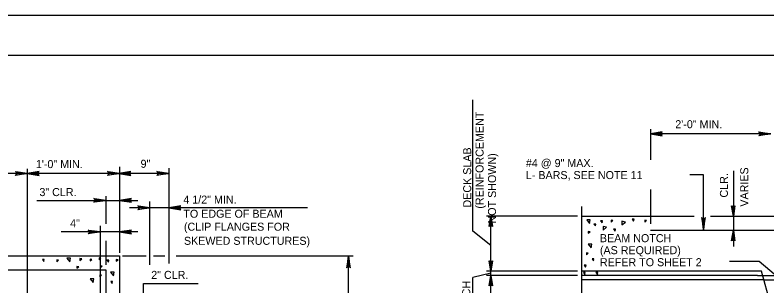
# Model space of a CAD drawing. Extents: x 640009 to 641706, y 298547 to 299735.
# Drawn here: x 640180 to 640461.6, y 299633.8 to 299735.2 of the extents above; entities that cross this region are included whole.
import ezdxf

# ---------------------------------------------------------------- set-up
doc = ezdxf.new("R2010")
doc.units = 0
doc.layers.add('1', color=7, linetype='Continuous')
doc.layers.add('PLT-BNDY', color=7, linetype='Continuous')

msp = doc.modelspace()

# ---------------------------------------------------------------- linework, layer by layer
at = {"layer": '1'}
for p, q in [((640049.47, 299720.17), (640835.47, 299720.17)), ((640049.47, 299720.17), (640835.47, 299720.17)), ((640351.47, 299654.25), (640351.47, 299703.42)), ((640417.97, 299692.45), (640417.97, 299680.94)), ((640463.05, 299690.72), (640417.97, 299690.72)), ((640184.59, 299675.91), (640139.52, 299675.91)), ((640184.52, 299677.64), (640184.52, 299626.29)), ((640219.09, 299675.91), (640184.59, 299675.91)), ((640237.59, 299675.91), (640218.97, 299675.91)), ((640219.09, 299678.41), (640219.09, 299646.17)), ((640237.72, 299642.19), (640237.72, 299677.91)), ((640449.03, 299676.81), (640449.03, 299648.54)), ((640437.84, 299675.32), (640432.75, 299675.32)), ((640437.84, 299654.84), (640437.84, 299675.32)), ((640213.97, 299667.39), (640213.97, 299657.05)), ((640417.97, 299669.87), (640417.97, 299657.02)), ((640188.12, 299665.79), (640225.99, 299665.79)), ((640230.47, 299641.63), (640230.47, 299665.42)), ((640230.47, 299663.05), (640222.84, 299663.05)), ((640289.49, 299663.05), (640230.47, 299663.05)), ((640392.22, 299622.96), (640392.22, 299663.55)), ((640390.66, 299659.84), (640356.62, 299659.84)), ((640358.25, 299629.1), (640358.25, 299659.84)), ((640392.22, 299659.84), (640434.34, 299659.84)), ((640440.51, 299659.84), (640497.47, 299659.84)), ((640211.84, 299656.21), (640211.84, 299625.33)), ((640225.99, 299653.96), (640197.29, 299653.96)), ((640358.25, 299648.91), (640351.47, 299654.25)), ((640417.97, 299654.59), (640453.97, 299654.59)), ((640453.97, 299654.59), (640492.22, 299654.59)), ((640213.97, 299650.6), (640213.97, 299641.65)), ((640113.97, 299645.05), (640219.09, 299645.05)), ((640219.09, 299645.05), (640219.09, 299612.05)), ((640220.2, 299645.05), (640229.09, 299645.05)), ((640231.84, 299645.05), (640236.09, 299645.05)), ((640240.35, 299645.05), (640306.65, 299645.05)), ((640304.9, 299612.05), (640304.9, 299645.05)), ((640458.71, 299642.91), (640447.59, 299642.91)), ((640474.68, 299629.38), (640458.71, 299642.91)), ((640175.59, 299639.8), (640213.97, 299639.8)), ((640213.97, 299639.8), (640213.97, 299621.92)), ((640390.66, 299639.34), (640356.62, 299639.34)), ((640459.59, 299639.34), (640392.22, 299639.34)), ((640485.09, 299545.46), (640459.59, 299639.34)), ((640358.25, 299638.59), (640351.47, 299636.93)), ((640351.47, 299617.09), (640351.47, 299636.93)), ((640390.66, 299637.71), (640356.62, 299637.71)), ((640458.09, 299637.71), (640392.22, 299637.71)), ((640458.09, 299637.71), (640490.22, 299637.71)), ((640228.09, 299597.69), (640228.09, 299634.64)), ((640228.09, 299634.64), (640248.51, 299634.64)), ((640460.47, 299636.09), (640392.22, 299636.09)), ((640460.48, 299636.09), (640490.22, 299636.09))]:
    msp.add_line(p, q, dxfattribs=at)
for points in [[(640422.21, 299691.26), (640422.04, 299690.95), (640417.97, 299690.72), (640422.21, 299691.26), (640422.42, 299691.45), (640417.97, 299690.72), (640422.04, 299690.53), (640422.2, 299690.22), (640417.97, 299690.72), (640422.42, 299690), (640422.2, 299690.22)], [(640458.76, 299691.25), (640458.93, 299690.93), (640463, 299690.71), (640458.76, 299691.25), (640458.55, 299691.43), (640463, 299690.71), (640458.93, 299690.51), (640458.78, 299690.21), (640463, 299690.71), (640458.55, 299689.98), (640458.78, 299690.21)], [(640180.31, 299676.43), (640180.48, 299676.12), (640184.55, 299675.89), (640180.31, 299676.43), (640180.09, 299676.62), (640184.55, 299675.89), (640180.48, 299675.69), (640180.32, 299675.39), (640184.55, 299675.89), (640180.09, 299675.17), (640180.32, 299675.39)], [(640188.76, 299676.43), (640188.58, 299676.12), (640184.52, 299675.89), (640188.76, 299676.43), (640188.97, 299676.62), (640184.52, 299675.89), (640188.58, 299675.69), (640188.74, 299675.39), (640184.52, 299675.89), (640188.97, 299675.17), (640188.74, 299675.39)], [(640214.81, 299676.43), (640214.98, 299676.12), (640219.05, 299675.89), (640214.81, 299676.43), (640214.59, 299676.62), (640219.05, 299675.89), (640214.98, 299675.69), (640214.82, 299675.39), (640219.05, 299675.89), (640214.59, 299675.17), (640214.82, 299675.39)], [(640223.13, 299676.43), (640222.96, 299676.12), (640218.89, 299675.89), (640223.13, 299676.43), (640223.34, 299676.62), (640218.89, 299675.89), (640222.96, 299675.69), (640223.12, 299675.39), (640218.89, 299675.89), (640223.34, 299675.17), (640223.12, 299675.39)], [(640221.83, 299676.26), (640221.71, 299676.05), (640219, 299675.9), (640221.83, 299676.26), (640221.97, 299676.38), (640219, 299675.9), (640221.71, 299675.77), (640221.82, 299675.56), (640219, 299675.9), (640221.97, 299675.42), (640221.82, 299675.56)], [(640233.31, 299676.43), (640233.48, 299676.12), (640237.55, 299675.89), (640233.31, 299676.43), (640233.09, 299676.62), (640237.55, 299675.89), (640233.48, 299675.69), (640233.32, 299675.39), (640237.55, 299675.89), (640233.09, 299675.17), (640233.32, 299675.39)], [(640209.73, 299666.33), (640209.9, 299666.01), (640213.97, 299665.79), (640209.73, 299666.33), (640209.51, 299666.52), (640213.97, 299665.79), (640209.9, 299665.59), (640209.74, 299665.29), (640213.97, 299665.79), (640209.51, 299665.07), (640209.74, 299665.29)], [(640223.34, 299666.33), (640223.16, 299666.01), (640219.09, 299665.79), (640223.34, 299666.33), (640223.55, 299666.52), (640219.09, 299665.79), (640223.16, 299665.59), (640223.32, 299665.29), (640219.09, 299665.79), (640223.55, 299665.07), (640223.32, 299665.29)], [(640226.18, 299663.57), (640226.36, 299663.25), (640230.43, 299663.03), (640226.18, 299663.57), (640225.97, 299663.76), (640230.43, 299663.03), (640226.36, 299662.83), (640226.2, 299662.53), (640230.43, 299663.03), (640225.97, 299662.31), (640226.2, 299662.53)], [(640241.88, 299663.57), (640241.71, 299663.25), (640237.64, 299663.03), (640241.88, 299663.57), (640242.09, 299663.76), (640237.64, 299663.03), (640241.71, 299662.83), (640241.87, 299662.53), (640237.64, 299663.03), (640242.09, 299662.31), (640241.87, 299662.53)], [(640449.53, 299663.59), (640449.28, 299663.46), (640449.03, 299659.84), (640449.53, 299663.59), (640449.65, 299663.71), (640449.03, 299659.84), (640448.9, 299663.46), (640448.65, 299663.59), (640449.03, 299659.84), (640448.4, 299663.71), (640448.65, 299663.59)], [(640357.75, 299656.09), (640358.12, 299656.21), (640358.25, 299659.84), (640357.75, 299656.09), (640357.62, 299655.96), (640358.25, 299659.84), (640358.5, 299656.21), (640358.75, 299656.09), (640358.25, 299659.84), (640358.87, 299655.96), (640358.75, 299656.09)], [(640437.32, 299659.13), (640437.64, 299658.95), (640437.86, 299654.88), (640437.32, 299659.13), (640437.14, 299659.34), (640437.86, 299654.88), (640438.06, 299658.95), (640438.36, 299659.11), (640437.86, 299654.88), (640438.59, 299659.34), (640438.36, 299659.11)], [(640207.6, 299654.5), (640207.78, 299654.18), (640211.84, 299653.96), (640207.6, 299654.5), (640207.39, 299654.68), (640211.84, 299653.96), (640207.78, 299653.76), (640207.62, 299653.46), (640211.84, 299653.96), (640207.39, 299653.23), (640207.62, 299653.46)], [(640223.34, 299654.5), (640223.16, 299654.18), (640219.09, 299653.96), (640223.34, 299654.5), (640223.55, 299654.68), (640219.09, 299653.96), (640223.16, 299653.76), (640223.32, 299653.46), (640219.09, 299653.96), (640223.55, 299653.23), (640223.32, 299653.46)], [(640448.53, 299650.84), (640448.9, 299650.96), (640449.03, 299654.59), (640448.53, 299650.84), (640448.4, 299650.71), (640449.03, 299654.59), (640449.28, 299650.96), (640449.53, 299650.84), (640449.03, 299654.59), (640449.65, 299650.71), (640449.53, 299650.84)], [(640305.42, 299640.76), (640305.11, 299640.93), (640304.89, 299645), (640305.42, 299640.76), (640305.61, 299640.55), (640304.89, 299645), (640304.69, 299640.93), (640304.38, 299640.78), (640304.89, 299645), (640304.16, 299640.55), (640304.38, 299640.78)], [(640358.75, 299643.09), (640358.5, 299642.96), (640358.25, 299639.34), (640358.75, 299643.09), (640358.87, 299643.21), (640358.25, 299639.34), (640358.12, 299642.96), (640357.87, 299643.09), (640358.25, 299639.34), (640357.62, 299643.21), (640357.87, 299643.09)], [(640357.75, 299633.96), (640358.12, 299634.09), (640358.25, 299637.71), (640357.75, 299633.96), (640357.62, 299633.84), (640358.25, 299637.71), (640358.5, 299634.09), (640358.75, 299633.96), (640358.25, 299637.71), (640358.87, 299633.84), (640358.75, 299633.96)]]:
    msp.add_lwpolyline(points, dxfattribs=at)
for points in [[(640394.09, 299658.46), (640395.09, 299657.09), (640395.34, 299658.46)], [(640396.72, 299656.84), (640397.34, 299656.21), (640397.47, 299656.84)], [(640399.22, 299658.09), (640399.84, 299657.34), (640399.97, 299658.09)], [(640403.22, 299657.59), (640403.84, 299658.21), (640403.22, 299658.34)], [(640407.22, 299656.59), (640408.59, 299657.59), (640407.22, 299657.96)], [(640411.09, 299658.71), (640411.59, 299657.96), (640411.84, 299658.71)], [(640415.84, 299657.59), (640416.47, 299658.21), (640415.84, 299658.34)], [(640394.59, 299653.46), (640395.34, 299653.96), (640394.59, 299654.09)], [(640400.24, 299654.63), (640401.49, 299655.75), (640400.24, 299656)], [(640404.09, 299654.96), (640404.72, 299654.21), (640404.84, 299654.96)], [(640394.59, 299649.46), (640395.72, 299648.09), (640395.97, 299649.46)], [(640393.97, 299645.46), (640394.59, 299646.09), (640393.97, 299646.21)], [(640190.22, 299643.67), (640190.72, 299642.92), (640190.84, 299643.67)], [(640195.59, 299642.8), (640196.22, 299643.42), (640195.59, 299643.55)], [(640199.34, 299644.2), (640200.47, 299642.83), (640200.72, 299644.2)], [(640204.22, 299643.3), (640204.97, 299643.92), (640204.22, 299644.05)], [(640208.09, 299643.2), (640208.72, 299643.7), (640208.09, 299643.83)], [(640211.47, 299643.55), (640212.09, 299644.17), (640211.47, 299644.3)], [(640214.31, 299643.45), (640214.93, 299642.7), (640215.06, 299643.45)], [(640217.84, 299643.05), (640218.59, 299643.55), (640217.84, 299643.67)], [(640396.09, 299643.96), (640396.59, 299643.21), (640396.72, 299643.96)], [(640203.07, 299640.4), (640203.82, 299640.9), (640203.07, 299641.03)], [(640211.86, 299640.65), (640212.61, 299641.15), (640211.86, 299641.28)], [(640393.09, 299641.59), (640393.59, 299640.84), (640393.84, 299641.59)], [(640208.09, 299636.42), (640209.22, 299635.05), (640209.47, 299636.42)], [(640211.72, 299637.17), (640212.34, 299637.8), (640211.72, 299637.92)], [(640215.72, 299638.92), (640216.84, 299637.55), (640217.09, 299638.92)], [(640392.84, 299638.84), (640393.34, 299638.09), (640393.47, 299638.84)], [(640397.47, 299638.84), (640398.09, 299638.09), (640398.22, 299638.84)], [(640215.84, 299635.42), (640216.34, 299634.67), (640216.47, 299635.42)]]:
    msp.add_lwpolyline(points, close=True, dxfattribs=at)
at = {"layer": 'PLT-BNDY'}
msp.add_lwpolyline([(640009.47, 299735.17), (640850.47, 299735.17), (640850.47, 299141.17), (640009.47, 299141.17)], close=True, dxfattribs=at)

# ---------------------------------------------------------------- texts
at = {"layer": '1'}
for s, p in [('(REINFORCEMENT', (640355.48, 299662.69)), ('DECK SLAB', (640350.84, 299663.11)), ('   NOT SHOWN)', (640360.13, 299653.79)), ('VARIES', (640454.62, 299663.44)), ('CLR.', (640447.01, 299666.85)), ('HAUNCH', (640350.48, 299618.5))]:
    msp.add_text(s, height=3, rotation=90, dxfattribs=at).set_placement(p)
for s, p in [('2\'-0" MIN.', (640427.29, 299692.81)), ('#4 @ 9" MAX.', (640371.32, 299678.26)), ('1\'-0" MIN.', (640187.77, 299677.88)), ('9"', (640227, 299678.01)), ('L- BARS, SEE NOTE 11', (640371.32, 299673.77)), ('3" CLR.', (640189.1, 299667.4)), ('4 1/2" MIN.', (640243.02, 299664.59)), ('TO EDGE OF BEAM', (640243.02, 299659.3)), ('4"', (640200.61, 299655.74)), ('(CLIP FLANGES FOR', (640243.24, 299654.44)), ('SKEWED STRUCTURES)', (640243.24, 299649.16)), ('BEAM NOTCH', (640399.05, 299650.15)), ('(AS REQUIRED)', (640399.05, 299645.65)), ('REFER TO SHEET 2', (640399.05, 299641.15)), ('2" CLR.', (640230.98, 299636.4))]:
    msp.add_text(s, height=3, dxfattribs=at).set_placement(p)

doc.saveas('drawing.dxf')
